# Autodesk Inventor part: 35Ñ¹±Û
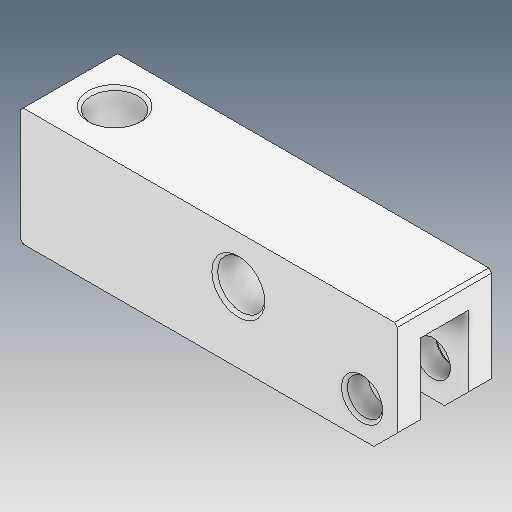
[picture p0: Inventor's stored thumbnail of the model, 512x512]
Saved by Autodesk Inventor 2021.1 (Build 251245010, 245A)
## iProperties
Created: 2021-05
Part Number: 35Ñ¹±Û
Material: Ogólny
Document SubType Name: Modeling
Designer: user
Density: 1 g/cm^3
Appearance: Domyślna
Author: user
Revision Number: ÈÎºÎ
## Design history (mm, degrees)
feature "ÊäÈë1"
node "Bryła1"
